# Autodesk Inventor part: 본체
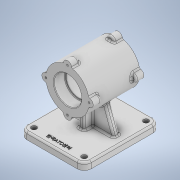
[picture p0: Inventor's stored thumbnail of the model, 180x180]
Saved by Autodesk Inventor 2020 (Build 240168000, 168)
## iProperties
Created: 2022-11
Part Number: 본체
Material: 일반
Document SubType Name: Modeling
Designer: owner
Density: 1 g/cm^3
Appearance: 기본값
Mass: 449.997 g
Surface Area: 797.002 cm^2
Volume: 449.997 cm^3
Author: owner
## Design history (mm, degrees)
sketch "스케치1"
  geometry: C1 r 37 at (0, 0); 1 further point
  constraints: 1 centre point, 1 coincident
  dimensions: "d0" = 74 diameter of C1
extrude "돌출1" new body sketch "스케치1" stored distance "d1" = 87; taper "d3" = 0 deg; dims "d2" = 5, "d4" = 0
node "작업 평면1"
sketch "스케치2"
  geometry: L1 (-37, -43.5)-(37, -43.5) reference; L2 (37, 43.5)-(-37, 43.5) reference; L3 (-55, -60)-(55, -60); L4 (55, -60)-(55, 70); L5 (55, 70)-(-55, 70); L6 (-55, 70)-(-55, -60); 2 further points
  constraints: 8 end point, 2 parallel, 1 horizontal, 1 midpoint, 1 perpendicular, 1 vertical alignment
  dimensions: "d6" = 130 distance of L5.end L3.start; "d7" = 110 distance of L4.end L5.end; "d9" = 70 distance of point (0, 0) point (0, 70)
extrude "돌출2" join sketch "스케치2" distance "d10" = 12; taper "d11" = 0 deg
sketch "스케치3"
  geometry: L1 (-55, -82)-(55, -82) reference; L2 (55, -82)-(55, -70) reference; L3 (-55, -70)-(55, -70) reference; L4 (-55, -82)-(-55, -70) reference; L5 (-55, -70)-(55, -70) reference; L6 (-41, -70)-(-25.336, -26.964); L7 (41, -70)-(25.336, -26.964); A1 r 37 centre (0, 0) between (-25.336, -26.964) and (25.336, -26.964) reference; 3 further points
  constraints: 4 end point, 2 point on circle, 2 point on line
  dimensions: "d12" = 110 deg angle of L3 L6; "d13" = 110 deg angle of L3 L7; "d14" = 14 distance from line of L4 L6.start; "d15" = 14 distance from line of L2 L7.start
extrude "돌출3" join sketch "스케치3" stored distance "d16" = 10; taper "d17" = 0 deg
sketch "스케치4"
  geometry: L1 (-82, 70)-(-82, -60) reference; L2 (-82, -60)-(-70, -60) reference; L3 (-70, 70)-(-70, -60) reference; L4 (-82, 70)-(-70, 70) reference; L5 (-26.964, 5)-(-26.964, -5) reference; L6 (-70, 5)-(-26.964, 5) reference; L7 (-70, -5)-(-70, 5) reference; L8 (-26.964, -5)-(-70, -5) reference; L9 (-70, -60)-(-70, 70) reference; L10 (-70, 20)-(-34.867, 20); 2 further points
  constraints: 2 end point, 2 point on line, 1 perpendicular
  dimensions: "d18" = 20 distance of point (-70, 0) L10.start
feature "리브1" sketch "스케치4" dims "d19" = 1, "d20" = 10, "d21" = 0, "d22" = 0, "d23" = 1, "d24" = 1
sketch "스케치5"
  geometry: C1 r 37 at (0, 0) reference; 2 further points
  constraints: 1 coincident
hole "구멍1" sketch "스케치5" at (0, 0) diameter "d25" = 42; stored, may be unused: countersink angle "d29" = 90 deg, drill point angle "d31" = 118 deg; dims "d26" = 8, "d27" = 47, "d28" = 19, "d30" = 10
sketch "스케치6"
  geometry: C1 r 37 at (0, 0) reference; 2 further points
  constraints: 1 coincident
hole "구멍2" sketch "스케치6" at (0, 0) diameter "d32" = 47; stored, may be unused: countersink angle "d36" = 90 deg, drill point angle "d38" = 0 deg; dims "d33" = 8, "d34" = 47, "d35" = 19, "d37" = 19
sketch "스케치7"
  geometry: C1 r 7 at (0, 37); 4 further points
  constraints: 1 centre point, 1 vertical alignment, 2 other
  dimensions: "d39" = 14 diameter of C1
extrude "돌출4" join sketch "스케치7" distance "d40" = 14; taper "d41" = 0 deg
sketch "스케치9"
  geometry: A1 r 7 centre (0, 37) between (6.969, 36.338) and (-6.969, 36.338) reference; 2 further points
  constraints: 1 coincident
hole "구멍3" sketch "스케치9" at (0, 37) diameter "d45" = 3.242; stored, may be unused: countersink angle "d49" = 90 deg, drill point angle "d51" = 118 deg; dims "d46" = 8, "d47" = 47, "d48" = 19, "d50" = 10
fillet "모깎기1" dims "d55" = 3
fillet "모깎기2" dims "d56" = 3
fillet "모깎기3" dims "d60" = 12
sketch "스케치10"
  geometry: A1 r 12 centre (-43, -58) between (-55, -58) and (-43, -70) reference; A2 r 12 centre (43, -58) between (43, -70) and (55, -58) reference; A3 r 12 centre (43, 48) between (55, 48) and (43, 60) reference; A4 r 12 centre (-43, 48) between (-43, 60) and (-55, 48) reference; 6 further points
  constraints: 4 coincident
hole "구멍4" sketch "스케치10" at (-43, -58), (43, -58), (43, 48), (-44.092, 47.154), (-43, 48) diameter "d61" = 9; stored, may be unused: countersink angle "d65" = 90 deg, drill point angle "d67" = 118 deg; dims "d62" = 8, "d63" = 47, "d64" = 19, "d66" = 10
fillet "모깎기4" dims "d68" = 3
fillet "모깎기5" dims "d69" = 1
fillet "모깎기6" dims "d70" = 3
fillet "모깎기7" dims "d71" = 3
chamfer "모따기1" distance "d72" = 1; stored, may be unused: second distance "d73" = 2, angle "d74" = 45 deg
sketch "스케치11"
  geometry: L1 (-43, -70)-(43, -70) reference; 3 further points
  constraints: 1 midpoint, 1 vertical alignment, 1 other
  dimensions: "d75" = 12 distance from line of L1 point (0, -58)
feature "엠보싱1" sketch "스케치11" dims "d76" = 0.5, "d77" = 0
node "솔리드1"
mirror "미러1"
pattern_circular "원형 패턴3" dims "d58" = 360 deg
mirror "미러2"
node "투영된 루프1"
node "투영된 루프2"
node "투영된 루프3"
node "투영된 루프4"
node "투영된 루프5"
feature "A9D066F2-1C7D-4E18-AEED-F7BC21143FA4" dims "d25" = 42, "d26" = 8, "d27" = 47, "d28" = 19, "d29" = 90 deg, "d30" = 10, "d31" = 118 deg
other parameters: "d5" = -82
